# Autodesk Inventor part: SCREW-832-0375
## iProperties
Created: 2007-08
Part Number: SCREW-832-0375
Material: Stainless Steel
Document SubType Name: Modeling
Density: 8.08 g/cm^3
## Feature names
1. Base1
